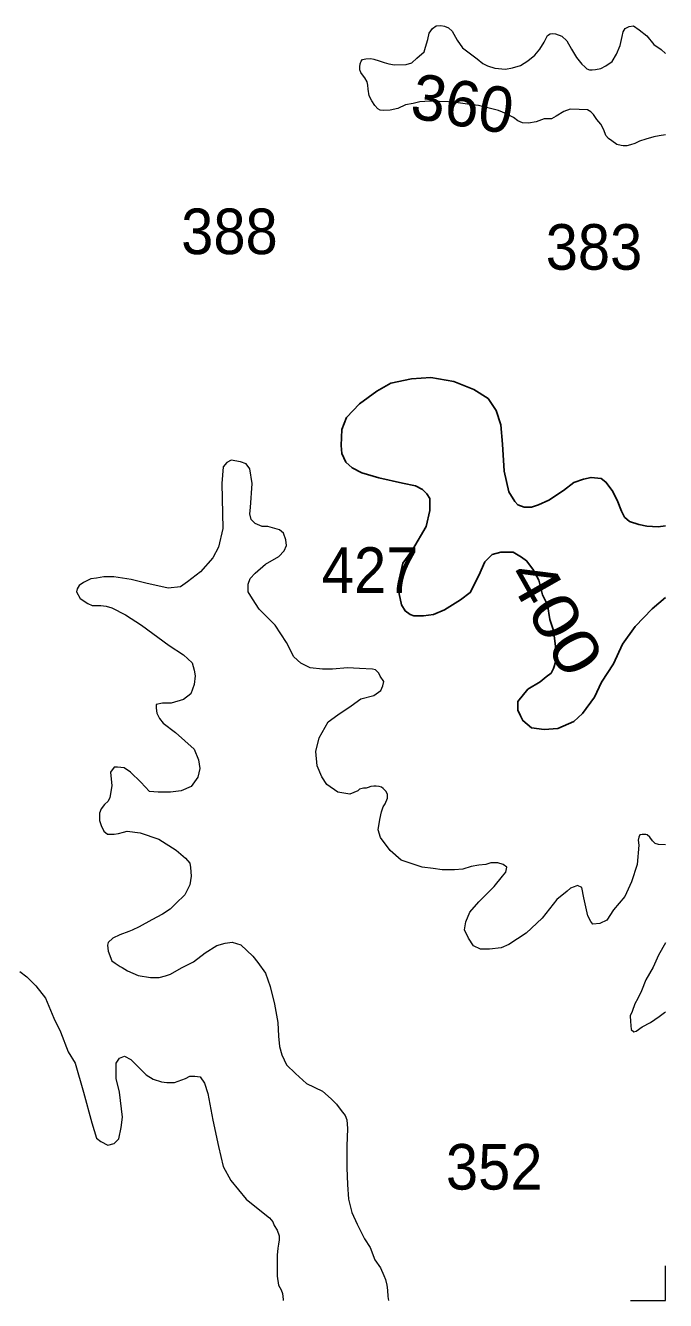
# Model space of a CAD drawing. Extents: x 445.4 to 500, y 8728.7 to 8784.
# Drawn here: x 497.752 to 500, y 8728.72 to 8733.195 of the extents above; entities that cross this region are included whole.
import ezdxf
from ezdxf.enums import TextEntityAlignment as Align

# ---------------------------------------------------------------- set-up
doc = ezdxf.new("R2010")
doc.units = 0
doc.header["$LTSCALE"] = 0.064
for name, color, linetype, lineweight in [('1', 7, 'Continuous', 25), ('2', 7, 'Continuous', 13), ('63', 7, 'Continuous', 13)]:
    doc.layers.add(name, color=color, linetype=linetype, lineweight=lineweight)
doc.layers.add('21', color=7, linetype='Continuous')
doc.layers.add('61', color=7, linetype='Continuous')

msp = doc.modelspace()

# ---------------------------------------------------------------- linework, layer by layer
at = {"layer": '1'}
msp.add_lwpolyline([(500, 8731.1871), (499.953, 8731.1479), (499.8931, 8731.0858), (499.8493, 8731.0237), (499.817, 8730.9546), (499.7755, 8730.8902), (499.7501, 8730.8373), (499.7082, 8730.7803), (499.6775, 8730.7523), (499.6216, 8730.7272), (499.574, 8730.7244), (499.5293, 8730.73), (499.4985, 8730.7551), (499.4902, 8730.7719), (499.4818, 8730.7924), (499.4818, 8730.8225), (499.5162, 8730.8654), (499.5593, 8730.8912), (499.5808, 8730.9084), (499.598, 8730.9213), (499.6066, 8730.9384), (499.6152, 8730.9642), (499.6152, 8731.0072), (499.6066, 8731.0716), (499.5937, 8731.1103), (499.5851, 8731.1618), (499.5679, 8731.1962), (499.555, 8731.2477), (499.5334, 8731.2864), (499.5119, 8731.3164), (499.4947, 8731.3293), (499.4646, 8731.3465), (499.4216, 8731.3465), (499.3914, 8731.3379), (499.3656, 8731.3121), (499.3441, 8731.2649), (499.314, 8731.2048), (499.2795, 8731.179), (499.2236, 8731.1446), (499.1849, 8731.1274), (499.1504, 8731.1231), (499.116, 8731.1231), (499.1031, 8731.1274), (499.0859, 8731.1403), (499.073, 8731.1618), (499.0644, 8731.2005), (499.0644, 8731.252), (499.0773, 8731.3078), (499.1117, 8731.3551), (499.1591, 8731.4367), (499.172, 8731.4926), (499.1722, 8731.5347), (499.1622, 8731.5508), (499.1461, 8731.5668), (499.122, 8731.5788), (499.0759, 8731.5888), (498.9936, 8731.6069), (498.9334, 8731.6249), (498.8992, 8731.6429), (498.8772, 8731.663), (498.8631, 8731.693), (498.8611, 8731.7211), (498.8631, 8731.7772), (498.8792, 8731.8192), (498.9253, 8731.8673), (498.9855, 8731.9114), (499.0357, 8731.9395), (499.108, 8731.9555), (499.1762, 8731.9595), (499.2565, 8731.9455), (499.3268, 8731.9174), (499.377, 8731.8854), (499.4051, 8731.8433), (499.4211, 8731.7932), (499.4271, 8731.7251), (499.4332, 8731.6309), (499.4492, 8731.5588), (499.4713, 8731.5247), (499.4813, 8731.5127), (499.5034, 8731.5047), (499.5295, 8731.5047), (499.5536, 8731.5127), (499.5897, 8731.5287), (499.6419, 8731.5628), (499.6781, 8731.5908), (499.7122, 8731.6028), (499.7383, 8731.6089), (499.7744, 8731.6049), (499.7905, 8731.5928), (499.8125, 8731.5628), (499.8306, 8731.5287), (499.8459, 8731.49), (499.856, 8731.4699), (499.874, 8731.4539), (499.9062, 8731.4439), (499.9343, 8731.4379), (499.9744, 8731.4359), (500, 8731.4389)], dxfattribs=at)
at = {"layer": '2'}
for points in [[(500, 8732.8119), (499.9774, 8732.8082), (499.9585, 8732.804), (499.9305, 8732.7963), (499.9089, 8732.7894), (499.8921, 8732.781), (499.8767, 8732.7761), (499.8642, 8732.7733), (499.8509, 8732.7733), (499.8439, 8732.774), (499.8292, 8732.7775), (499.8118, 8732.7907), (499.7992, 8732.7984), (499.7901, 8732.8096), (499.7831, 8732.8291), (499.7733, 8732.8486), (499.7593, 8732.8654), (499.7475, 8732.8828), (499.7377, 8732.8926), (499.7265, 8732.8996), (499.6972, 8732.9005), (499.6655, 8732.9019), (499.6424, 8732.8933), (499.6165, 8732.8774), (499.5992, 8732.8674), (499.5733, 8732.8674), (499.5453, 8732.8573), (499.5183, 8732.8521), (499.4973, 8732.8532), (499.4818, 8732.861), (499.4663, 8732.872), (499.4419, 8732.8853), (499.4132, 8732.8963), (499.3711, 8732.9074), (499.3434, 8732.914), (499.3124, 8732.9184), (499.2715, 8732.9239), (499.2372, 8732.9272), (499.1719, 8732.9295), (499.1365, 8732.9272), (499.1132, 8732.9217), (499.0866, 8732.9162), (499.0601, 8732.904), (499.0324, 8732.8985), (499.0103, 8732.8974), (498.9981, 8732.8985), (498.9892, 8732.9029), (498.9793, 8732.914), (498.9682, 8732.9306), (498.9594, 8732.9482), (498.956, 8732.9714), (498.9549, 8732.9858), (498.9516, 8732.998), (498.9439, 8733.0112), (498.9361, 8733.0223), (498.9295, 8733.03), (498.9262, 8733.0399), (498.9262, 8733.0499), (498.9273, 8733.0609), (498.9306, 8733.0698), (498.9361, 8733.0753), (498.9472, 8733.0786), (498.9649, 8733.0797), (498.976, 8733.0775), (498.9948, 8733.0709), (499.0114, 8733.0653), (499.028, 8733.0609), (499.0479, 8733.0576), (499.0889, 8733.0587), (499.1088, 8733.0642), (499.1265, 8733.0808), (499.1521, 8733.1024), (499.1565, 8733.1189), (499.1654, 8733.1466), (499.1698, 8733.1687), (499.182, 8733.1852), (499.1941, 8733.1941), (499.2108, 8733.1952), (499.224, 8733.193), (499.2373, 8733.1874), (499.2506, 8733.1753), (499.2683, 8733.1432), (499.2868, 8733.117), (499.3384, 8733.0781), (499.3585, 8733.0624), (499.3743, 8733.054), (499.4006, 8733.0456), (499.4385, 8733.0424), (499.4627, 8733.0466), (499.4912, 8733.055), (499.5164, 8733.0708), (499.5407, 8733.0908), (499.5586, 8733.1118), (499.5733, 8733.137), (499.586, 8733.1602), (499.5944, 8733.1654), (499.6028, 8733.1675), (499.6133, 8733.1665), (499.6355, 8733.1581), (499.6534, 8733.1412), (499.6692, 8733.1118)], [(499.6692, 8733.1118), (499.6871, 8733.0834), (499.706, 8733.0592), (499.7166, 8733.0498), (499.7239, 8733.0435), (499.7334, 8733.0392), (499.7429, 8733.0392), (499.7545, 8733.0403), (499.7724, 8733.0445), (499.7903, 8733.054), (499.8124, 8733.0687), (499.8282, 8733.095), (499.8406, 8733.1251), (499.8478, 8733.1571), (499.8508, 8733.1731), (499.858, 8733.1847), (499.8726, 8733.192), (499.8872, 8733.1935), (499.9076, 8733.1804), (499.9338, 8733.1586), (499.9586, 8733.128), (499.9848, 8733.1106), (500, 8733.0967)], [(498.8104, 8730.5311), (498.7934, 8730.5579), (498.7763, 8730.5968), (498.7713, 8730.6467), (498.7835, 8730.6953), (498.8152, 8730.7512), (498.8493, 8730.7756), (498.8956, 8730.8072), (498.9297, 8730.8315), (498.976, 8730.8437), (499.0004, 8730.8607), (499.0077, 8730.8777), (499.0101, 8730.8923), (498.998, 8730.9118), (498.9931, 8730.9215), (498.9809, 8730.9337), (498.9711, 8730.9361), (498.9248, 8730.9385), (498.8834, 8730.941), (498.8298, 8730.9361), (498.7957, 8730.9361), (498.7518, 8730.941), (498.7195, 8730.9568), (498.6951, 8730.9787), (498.6683, 8731.0298), (498.6293, 8731.0906), (498.5733, 8731.1465), (498.5489, 8731.183), (498.5343, 8731.2074), (498.5343, 8731.2341), (498.5416, 8731.2536), (498.5587, 8731.273), (498.5952, 8731.3046), (498.6415, 8731.3314), (498.661, 8731.3509), (498.6683, 8731.3703), (498.6659, 8731.3898), (498.6588, 8731.4128), (498.6442, 8731.425), (498.6027, 8731.4371), (498.5832, 8731.4371), (498.5589, 8731.4468), (498.5442, 8731.4614), (498.5394, 8731.4809), (498.5418, 8731.5028), (498.5479, 8731.5881), (498.5403, 8731.6387), (498.5276, 8731.6564), (498.5073, 8731.664), (498.4743, 8731.6691), (498.4591, 8731.6615), (498.4464, 8731.6463), (498.4414, 8731.5881), (498.4457, 8731.4299), (498.4305, 8731.3641), (498.4102, 8731.3261), (498.3671, 8731.278), (498.3214, 8731.2426), (498.2961, 8731.2249), (498.253, 8731.2198), (498.1744, 8731.2375), (498.1237, 8731.2502), (498.0628, 8731.2603), (498.0273, 8731.2603), (498.0019, 8731.2553), (497.9817, 8731.2527), (497.9563, 8731.2401), (497.9411, 8731.23), (497.9335, 8731.2173), (497.9309, 8731.2072), (497.9436, 8731.1844), (497.9715, 8731.1667), (497.9867, 8731.1591), (498.0019, 8731.1591), (498.0172, 8731.1591), (498.0349, 8731.1566), (498.0552, 8731.1515), (498.1034, 8731.1262), (498.1592, 8731.0907), (498.2561, 8731.0188), (498.3068, 8730.9859), (498.3373, 8730.9581), (498.3449, 8730.9328), (498.3474, 8730.9125), (498.3449, 8730.8821), (498.3322, 8730.8492), (498.3068, 8730.829), (498.2637, 8730.8163), (498.2333, 8730.8163), (498.2105, 8730.8113), (498.2105, 8730.7986), (498.213, 8730.7809), (498.2232, 8730.7632), (498.2354, 8730.7467), (498.2785, 8730.7138), (498.3444, 8730.6556), (498.3597, 8730.6176), (498.3647, 8730.5872), (498.3571, 8730.5568), (498.3343, 8730.5239), (498.2988, 8730.5088)], [(498.2988, 8730.5088), (498.2608, 8730.5037), (498.2177, 8730.5037), (498.1872, 8730.5062), (498.1568, 8730.5388), (498.1213, 8730.5742), (498.0985, 8730.5894), (498.0756, 8730.5919), (498.063, 8730.5919), (498.0503, 8730.5742), (498.0554, 8730.5261), (498.0478, 8730.4856), (498.0427, 8730.473), (498.03, 8730.4603), (498.0173, 8730.4451), (498.0123, 8730.4299), (498.0123, 8730.4046), (498.0173, 8730.3869), (498.0275, 8730.3667), (498.0401, 8730.3565), (498.063, 8730.3565), (498.0782, 8730.3591), (498.0959, 8730.3641), (498.1086, 8730.3667), (498.1543, 8730.3616), (498.2202, 8730.3388), (498.281, 8730.3009), (498.314, 8730.273), (498.3292, 8730.2553), (498.3318, 8730.2401), (498.3343, 8730.2097), (498.3292, 8730.1794), (498.3115, 8730.1439), (498.2799, 8730.1135), (498.2596, 8730.0935), (498.2335, 8730.0757), (498.1961, 8730.0554), (498.151, 8730.0314), (498.1268, 8730.0201), (498.1155, 8730.0148), (498.0832, 8730.0028), (498.0584, 8729.9915), (498.0423, 8729.9763), (498.0404, 8729.9667), (498.0426, 8729.9464), (498.0553, 8729.9118), (498.0666, 8729.9033), (498.0847, 8729.8917), (498.0915, 8729.8886), (498.1101, 8729.8775), (498.1482, 8729.8606), (498.1914, 8729.853), (498.2216, 8729.853), (498.2435, 8729.8599), (498.2614, 8729.8654), (498.2998, 8729.8874), (498.3416, 8729.9087), (498.3827, 8729.9396), (498.4245, 8729.9657), (498.4533, 8729.974), (498.478, 8729.9781), (498.5088, 8729.9678), (498.55, 8729.9286), (498.5685, 8729.9059), (498.5952, 8729.8688), (498.6117, 8729.8214), (498.6261, 8729.7595), (498.6384, 8729.6955), (498.6405, 8729.6481), (498.6446, 8729.611), (498.6528, 8729.5821), (498.6693, 8729.547), (498.7001, 8729.5161), (498.7392, 8729.481), (498.7947, 8729.4542), (498.8256, 8729.4274), (498.8441, 8729.4088), (498.8605, 8729.3862), (498.8749, 8729.3697), (498.8808, 8729.3539), (498.8826, 8729.3235), (498.8808, 8729.261), (498.8808, 8729.186), (498.8826, 8729.127), (498.8862, 8729.0752), (498.8986, 8729.0288), (498.9164, 8728.9877), (498.9432, 8728.9359), (498.9628, 8728.9055), (498.9788, 8728.8626), (498.9984, 8728.8341), (499.0108, 8728.8073), (499.0162, 8728.793), (499.0215, 8728.7733), (499.0233, 8728.7555), (499.0251, 8728.734), (499.0268, 8728.7198)], [(500, 8730.3194), (499.9749, 8730.3205), (499.9638, 8730.3242), (499.9545, 8730.3334), (499.9453, 8730.3464), (499.936, 8730.3538), (499.9304, 8730.3556), (499.9175, 8730.3556), (499.9101, 8730.3538), (499.9064, 8730.3464), (499.9045, 8730.3353), (499.9064, 8730.3186), (499.9008, 8730.2502), (499.8804, 8730.1892), (499.8568, 8730.1377), (499.8178, 8730.0915), (499.7934, 8730.055), (499.7691, 8730.0428), (499.7447, 8730.0404), (499.7374, 8730.0501), (499.7276, 8730.0696), (499.713, 8730.1328), (499.7057, 8730.1693), (499.6911, 8730.1766), (499.6789, 8730.1717), (499.6667, 8730.1669), (499.6545, 8730.1571), (499.618, 8730.1279), (499.5668, 8730.0623), (499.5108, 8730.0088), (499.4498, 8729.9698), (499.423, 8729.9577), (499.3816, 8729.9528), (499.3499, 8729.9528), (499.3256, 8729.965), (499.3085, 8729.9917), (499.2939, 8730.0209), (499.2984, 8730.0487), (499.313, 8730.0828), (499.3447, 8730.1193), (499.3983, 8730.1728), (499.4275, 8730.2093), (499.4397, 8730.2238), (499.4421, 8730.2409), (499.43, 8730.2506), (499.4105, 8730.2555), (499.3861, 8730.2555), (499.369, 8730.2506), (499.3447, 8730.2482), (499.3179, 8730.2433), (499.2886, 8730.2336), (499.2594, 8730.2311), (499.2155, 8730.2311), (499.1838, 8730.236), (499.1448, 8730.2409), (499.1107, 8730.253), (499.0717, 8730.2652), (499.0327, 8730.2992), (498.9986, 8730.3455), (498.9913, 8730.3722), (498.9966, 8730.4076), (499.003, 8730.4348), (499.0086, 8730.4524), (499.015, 8730.4636), (499.0238, 8730.4828), (499.0238, 8730.4964), (499.019, 8730.5068), (499.0086, 8730.5164), (499.0022, 8730.5212), (498.9942, 8730.5244), (498.9837, 8730.5252), (498.9757, 8730.5252), (498.9653, 8730.5236), (498.9557, 8730.5204), (498.9485, 8730.518), (498.9388, 8730.518), (498.9252, 8730.5148), (498.9188, 8730.5084), (498.8909, 8730.4971), (498.8494, 8730.5044), (498.8104, 8730.5311)], [(500, 8729.9749), (499.9756, 8729.9324), (499.9563, 8729.8901), (499.9313, 8729.8458), (499.9159, 8729.8073), (499.9024, 8729.7803), (499.8928, 8729.7611), (499.8832, 8729.7342), (499.8755, 8729.7188), (499.8774, 8729.6995), (499.8793, 8729.6706), (499.8889, 8729.6629), (499.8966, 8729.6649), (499.9178, 8729.6803), (499.9467, 8729.6957), (499.9775, 8729.7168), (499.9967, 8729.7303), (500, 8729.7331)], [(497.7323, 8729.8751), (497.7568, 8729.8558), (497.7879, 8729.8248), (497.8228, 8729.781), (497.8512, 8729.7113), (497.8744, 8729.6623), (497.9016, 8729.5926), (497.9263, 8729.5532), (497.9556, 8729.4508), (497.9849, 8729.3436), (498.002, 8729.2899), (498.0167, 8729.2777), (498.0411, 8729.2655), (498.0631, 8729.2704), (498.0802, 8729.2875), (498.0875, 8729.3265), (498.0924, 8729.3631), (498.0826, 8729.4508), (498.0704, 8729.4996), (498.0704, 8729.5532), (498.0826, 8729.5703), (498.0997, 8729.5776), (498.1217, 8729.5654), (498.1486, 8729.5386), (498.1754, 8729.5118), (498.1999, 8729.4971), (498.2292, 8729.4874), (498.2487, 8729.4849), (498.2756, 8729.4849), (498.3146, 8729.4996), (498.3293, 8729.5069), (498.3464, 8729.5069), (498.3659, 8729.5045), (498.3806, 8729.4825), (498.3928, 8729.4459), (498.4099, 8729.3533), (498.4294, 8729.2607), (498.4465, 8729.19), (498.4734, 8729.1412), (498.5271, 8729.0754), (498.5865, 8729.0275), (498.6085, 8729.0104)], [(498.6085, 8729.0104), (498.6207, 8728.9958), (498.6256, 8728.9836), (498.6354, 8728.9665), (498.6427, 8728.947), (498.6427, 8728.9324), (498.6403, 8728.9178), (498.6378, 8728.9032), (498.6354, 8728.8788), (498.6354, 8728.852), (498.6354, 8728.8349), (498.6354, 8728.8056), (498.6403, 8728.774), (498.65, 8728.7569), (498.6549, 8728.7447), (498.6573, 8728.7228), (498.6574, 8728.7198)]]:
    msp.add_lwpolyline(points, dxfattribs=at)
at = {"layer": '63'}
msp.add_lwpolyline([(499.8768, 8728.7198), (500, 8728.7198), (500, 8728.8412)], dxfattribs=at)

# ---------------------------------------------------------------- texts
at = {"layer": '21', "width": 0.95}
for s, p in [('388', (498.2988, 8732.3926)), ('383', (499.5792, 8732.338)), ('352', (499.2287, 8729.1091))]:
    msp.add_text(s, height=0.16, dxfattribs=at).set_placement(p)
msp.add_text('427', height=0.16, dxfattribs=at).set_placement((499.132, 8731.2037), align=Align.RIGHT)
at = {"layer": '61'}
msp.add_text('360', height=0.16, rotation=350.63, dxfattribs=at).set_placement((499.2746, 8732.8423), align=Align.CENTER)
at = {"layer": '61', "width": 1.2}
msp.add_text('400', height=0.16, rotation=299.587, dxfattribs=at).set_placement((499.5448, 8731.0811), align=Align.CENTER)

doc.saveas('drawing.dxf')
